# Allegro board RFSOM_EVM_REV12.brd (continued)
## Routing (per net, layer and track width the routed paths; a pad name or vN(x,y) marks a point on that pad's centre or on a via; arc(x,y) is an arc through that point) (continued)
JTAG_TDI: length 112.4
  TOP w0.173: U5.4 389.38,16.86 389.93,17.41 v1(389.93,17.81) ; J2.F23 v1(321.98,62.56)
  ART05 w0.14: v1(389.93,17.81) 389.93,18.64 381.25,27.32 365.64,27.32 363.13,29.84 363.13,48.2 357.91,53.42 357.91,63.9 354.32,67.49 335,67.49 331.91,64.4 322.55,64.4 321.98,63.83 v1(321.98,62.56)
  BOTTOM w0.173: v1(389.93,17.81) R7.2
JTAG_TDO: length 105.7
  TOP w0.173: v1(387.09,15.03) 386.59,15.54 U6.4 ; J2.B25 v1(328.33,61.29)
  ART05 w0.14: v1(387.09,15.03) 386.2,14.15 358.33,14.15 356.55,15.93 356.55,35.16 353.45,38.26 353.45,51.96 354.2,52.71 354.2,53.64 353.19,54.66 337.31,54.66 330.68,61.29 v1(328.33,61.29)
  BOTTOM w0.173: R8.2 386.32,17.81 387.09,17.04 v1(387.09,15.03)
JTAG_TMS: length 113.6
  TOP w0.173: v1(384.3,15.03) 383.79,15.54 U3.4 ; J2.D26 v1(324.52,58.75)
  ART05 w0.14: v1(384.3,15.03) 384.85,15.58 387.16,15.58 387.53,15.21 387.53,13.09 386.56,12.12 362.94,12.12 361.92,13.13 349.68,13.13 345.34,17.48 345.34,27.21 343.83,28.71 343.83,35.14 346.14,37.45 346.14,42.9 344,45.04 344,46.34 330.64,59.7 327.4,59.7 325.86,58.17 325.11,58.17 v1(324.52,58.75)
  BOTTOM w0.173: v1(384.3,15.03) 384.3,17.25 383.74,17.81 R9.2
LEDG0: length 119.2
  TOP w0.173: J1.C13 v1(228.1,76.53)
  TOP w0.381: R24.1 v1(283.21,-18.28)
  BOTTOM w0.381: v1(283.21,-18.28) 283.21,-12.04 278.63,-7.46 278.63,23.21 235.98,65.86 235.98,68.65 v1(228.1,76.53)
LEDG1: length 154.8
  TOP w0.173: J1.G7 v1(221.75,84.15)
  TOP w0.381: R27.1 v1(292.07,-18.28)
  ART10 w0.381: v1(221.75,84.15) 222.36,83.54 225.34,83.54 226.04,84.23 226.04,85.45 226.67,86.08 251.94,86.08 292.07,45.95 v1(292.07,-18.28)
LEDG2: length 141.5
  TOP w0.173: J1.G13 v1(223.02,76.53)
  TOP w0.381: R30.1 v1(300.94,-18.28)
  BOTTOM w0.381: v1(300.94,-18.28) 297.9,-18.28 291,-11.38 291,26.51 240.37,77.14 223.62,77.14 v1(223.02,76.53)
LEDG3: length 168.7
  TOP w0.173: J1.F7 v1(223.02,84.15)
  TOP w0.381: R33.1 v1(309.8,-18.28)
  ART10 w0.381: v1(223.02,84.15) 223.69,84.83 224.63,84.83 225.11,85.31 225.11,86.38 226.09,87.36 263.28,87.36 309.8,40.83 v1(309.8,-18.28)
M2_DEV_CLKN: length 57.8
  TOP w0.114: v1(341.04,-5.37) 340.85,-5.56 arc(340.68,-5.67) 340.48,-5.71 340.45,-5.71 arc(340.25,-5.67) 340.08,-5.56 C76.2 ; U13.15 339.17,28.96 arc(339.06,28.93) 338.96,28.87 338.94,28.85 arc(338.85,28.79) 338.73,28.76 337.62,28.76 arc(337.5,28.82) 337.44,28.94 337.44,29.07 arc(337.48,29.26) 337.59,29.42 v1(337.75,29.58)
  ART10 w0.102: v1(341.04,-5.37) 341.29,-5.62 arc(341.39,-5.69) 341.51,-5.71 343.5,-5.71 arc(344.26,-5.56) 344.91,-5.12 arc(345.4,-4.4) 345.56,-3.55 345.56,31.02 arc(345.52,31.25) 345.39,31.44 344.78,32.05 arc(344.64,32.15) 344.47,32.18 343.1,32.18 arc(343.01,32.14) 342.98,32.05 arc(342.94,31.96) 342.85,31.93 342.7,31.93 arc(342.61,31.96) 342.57,32.05 arc(342.53,32.14) 342.44,32.18 342.29,32.18 arc(342.2,32.14) 342.16,32.05 arc(342.13,31.96) 342.04,31.93 341.88,31.93 arc(341.79,31.96) 341.76,32.05 arc(341.72,32.14) 341.63,32.18 341.48,32.18 arc(341.39,32.14) 341.35,32.05 arc(341.31,31.96) 341.22,31.93 341.07,31.93 arc(340.98,31.96) 340.94,32.05 arc(340.91,32.14) 340.82,32.18 340.67,32.18 arc(340.58,32.14) 340.54,32.05 arc(340.5,31.96) 340.41,31.93 340.26,31.93 arc(340.17,31.96) 340.13,32.05 arc(340.09,32.14) 340,32.18 339.85,32.18 arc(339.76,32.14) 339.73,32.05 arc(339.69,31.96) 339.6,31.93 339.45,31.93 arc(339.36,31.96) 339.32,32.05 arc(339.28,32.14) 339.19,32.18 338.54,32.18 arc(338.34,32.14) 338.18,32.03 337.68,31.53 arc(337.48,31.23) 337.41,30.88 337.41,30.15 arc(337.45,29.93) 337.57,29.75 v1(337.75,29.58)
M2_DEV_CLKP: length 57.8
  TOP w0.114: U13.16 339.17,28.31 arc(339.06,28.33) 338.96,28.39 338.94,28.41 arc(338.85,28.48) 338.73,28.5 337.62,28.5 arc(337.31,28.63) 337.18,28.94 337.18,28.98 arc(337.13,29.19) 337.01,29.37 336.83,29.56 v1(336.83,29.58) ; v1(341.04,-6.28) 340.89,-6.14 arc(340.75,-6.04) 340.58,-6.01 340.43,-6.01 arc(340.23,-6.05) 340.07,-6.16 C77.2
  ART10 w0.102: v1(341.04,-6.28) 341.29,-6.03 arc(341.39,-5.97) 341.51,-5.94 343.5,-5.94 arc(344.36,-5.77) 345.08,-5.29 arc(345.61,-4.49) 345.8,-3.55 345.8,31.02 arc(345.74,31.34) 345.55,31.61 344.94,32.22 arc(344.73,32.37) 344.47,32.42 338.54,32.42 arc(338.25,32.36) 338.01,32.2 337.51,31.7 arc(337.26,31.32) 337.17,30.88 337.17,30.15 arc(337.13,29.93) 337.01,29.75 v1(336.83,29.58)
M2_NVME_DET: length 2.5
  TOP w0.173: J17.69 R64.2
M2_PERST: length 154
  TOP w0.173: v1(349.71,49.78) 351.38,49.78 R63.2 ; v1(326.42,-5.23) 325.6,-4.41 J17.50 ; J2.F7 v1(321.98,84.15)
  ART10 w0.135: v1(326.42,-5.23) 329.36,-8.17 345.79,-8.17 350.82,-3.13 350.82,33.15 349.71,34.27 v1(349.71,49.78)
  BOTTOM w0.173: v1(349.71,49.78) 344.69,54.79 331.86,54.79 329.65,57 318.62,57 314.84,60.78 314.84,78.71 317.13,81 320.87,81 321.3,81.43 321.3,83.47 v1(321.98,84.15)
NVME_ACT: length 2.4
  TOP w0.173: J17.10 v1(325.6,5.59)
  BOTTOM w0.508: v1(325.6,5.59) 325.99,5.2 D8.2
OSCI: length 8.3
  TOP w0.173: C11.1 389.15,-4.55 Y1.2 389.16,-3.3 389.46,-3 389.46,0.36 389.2,0.61 U2.2
OSCO: length 10.7
  TOP w0.173: C14.1 392.86,-7.06 Y1.1 392.86,-3.73 390.8,-1.68 390.8,0.48 390.18,1.11 U2.3
PHY_LED_1000: length 41.8
  TOP w0.173: RL15.1 382.2,69.28 v1(382.49,68.99) 382.49,68.3 381.84,67.65 U12.22
  ART10 w0.508: J16.11 402.15,54.03 385.66,54.03 381.7,57.99 381.7,60.32 383.16,61.77 383.16,68.32 v1(382.49,68.99)
PHY_LED_ACT: length 29.8
  TOP w0.173: RL18.1 383.2,68.16 v1(382.49,67.46) 382.24,67.21 U12.21
  ART03 w0.508: J16.14 402.37,73.25 391.94,73.25 386.15,67.46 v1(382.49,67.46)
PHY_MDC: length 67.5
  TOP w0.173: J2.D24 v1(324.52,62.56) ; v1(373.5,61.49) 375.06,61.49 375.3,61.73 375.77,61.73 376.45,62.41 U12.40
  BOTTOM w0.173: v1(324.52,62.56) 325.26,61.82 327.02,61.82 327.89,62.69 327.89,69.1 328.15,69.35 329.79,69.35 333.21,65.93 337.35,65.93 344.58,58.71 368.24,58.71 371.02,61.49 v1(373.5,61.49)
PHY_MDINT: length 4.4
  TOP w0.173: RL11.1 384.2,67.97 383.66,67.44 383.66,66.5 383.18,66.01 U12.20
PHY_MDIO: length 68.3
  TOP w0.173: U12.39 377.21,62.81 377.16,62.76 376.4,62.76 376.12,63.04 RL10.1 374.49,63.04 v1(374.28,63.25) ; J2.E24 v1(323.25,62.56)
  BOTTOM w0.173: v1(374.28,63.25) 369.89,63.25 365.77,59.14 345.09,59.14 337.77,66.46 333.37,66.46 330.09,69.74 328.07,69.74 327.5,69.17 327.5,63.42 327.28,63.2 324.46,63.2 323.83,62.56 v1(323.25,62.56)
PHY_RX_CLK: length 133.6
  TOP w0.173: U12.31 377.64,66.01 377.47,66.18 377.47,68.21 376.94,68.73 v1(376.94,68.99) 376.82,68.99 376.2,69.61 RL21.1 ; J2.G21 v1(320.71,66.37)
  BOTTOM w0.173: v1(320.71,66.37) 320.23,66.85 319.58,66.85 319,67.44 319,73.05 319.5,73.55 324.58,73.55 328.06,77.03 330.07,77.03 330.81,76.29 331.31,76.29 331.72,76.7 331.72,78.34 331.92,78.54 332.21,78.54 332.41,78.34 332.41,76.15 332.61,75.95 332.9,75.95 333.1,76.15 333.1,78.34 333.3,78.54 333.59,78.54 333.79,78.34 333.79,76.15 334,75.95 334.28,75.95 334.54,76.21 334.54,78.52 334.78,78.75 335.06,78.75 335.24,78.58 335.24,76.12 335.41,75.95 335.66,75.95 335.93,76.21 335.93,78.52 336.16,78.75 336.44,78.75 336.62,78.58 336.62,76.12 336.79,75.95 337.05,75.95 337.31,76.21 337.31,78.52 337.54,78.75 337.82,78.75 338,78.58 338,76.12 338.17,75.95 338.43,75.95 338.69,76.21 338.69,78.52 338.92,78.75 339.21,78.75 339.38,78.58 339.38,76.12 339.55,75.95 339.81,75.95 340.07,76.21 340.07,78.52 340.3,78.75 340.59,78.75 340.76,78.58 340.76,76.12 340.94,75.95 341.19,75.95 341.39,76.15 341.39,78.34 341.6,78.54 341.88,78.54 342.08,78.34 342.08,76.15 342.29,75.95 342.57,75.95 342.77,76.15 342.77,78.34 342.98,78.54 343.26,78.54 343.47,78.34 343.47,76.15 343.67,75.95 360.45,75.95 362.36,77.86 366.95,77.86 367.55,77.27 367.55,73.38 367.81,73.12 368.1,73.12 369.67,74.69 369.96,74.69 370.16,74.49 370.16,74.2 368.59,72.63 368.59,72.34 368.79,72.14 369.08,72.14 370.65,73.71 370.94,73.71 371.14,73.51 371.14,73.22 369.57,71.65 369.57,71.36 371.94,68.99 v1(376.94,68.99)
PHY_RX_CTRL: length 135.8
  TOP w0.173: U12.30 378.64,67 378.48,67.16 v1(378.48,67.46) 378,67.94 378,68.79 377.2,69.59 RL17.1 ; J2.F21 v1(323.25,65.1)
  BOTTOM w0.173: v1(378.48,67.46) 377.49,68.46 371.37,68.46 366.1,73.72 364.83,73.72 364.63,73.93 364.63,74.09 364.45,74.26 364.11,74.26 363.93,74.09 363.93,73.93 363.73,73.72 361.5,73.72 361.3,73.93 361.3,75.14 361.11,75.33 360.82,75.33 360.61,75.12 360.61,74.03 360.4,73.82 360.12,73.82 359.92,74.02 359.92,75.14 359.73,75.33 359.44,75.33 359.23,75.12 359.23,74.03 359.02,73.82 358.73,73.82 358.54,74.02 358.54,75.14 358.35,75.33 358.06,75.33 357.85,75.12 357.85,74.03 357.64,73.82 357.35,73.82 357.15,74.02 357.15,75.14 356.96,75.33 356.68,75.33 356.46,75.12 356.46,74.03 356.26,73.82 355.88,73.82 355.68,74.02 355.68,75.13 355.49,75.32 355.21,75.32 354.99,75.1 354.99,74.03 354.79,73.82 354.5,73.82 354.3,74.02 354.3,75.13 354.11,75.32 353.83,75.32 353.61,75.1 353.61,74.03 353.4,73.82 353.12,73.82 352.92,74.02 352.92,75.13 352.73,75.32 352.44,75.32 352.23,75.1 352.23,74.03 352.02,73.82 351.74,73.82 351.54,74.02 351.54,75.13 351.35,75.32 351.06,75.32 350.85,75.1 350.85,74.03 350.64,73.82 350.35,73.82 350.16,74.02 350.16,75.13 349.97,75.32 349.68,75.32 349.46,75.1 349.46,74.03 349.26,73.82 348.97,73.82 348.77,74.02 348.77,75.13 348.58,75.32 348.3,75.32 348.08,75.1 348.08,74.03 347.88,73.82 347.59,73.82 347.39,74.02 347.39,75.13 347.2,75.32 346.92,75.32 346.7,75.1 346.7,74.03 346.5,73.82 346.21,73.82 346.01,74.02 346.01,75.13 345.82,75.32 345.53,75.32 345.32,75.1 345.32,74.03 345.11,73.82 344.83,73.82 344.63,74.02 344.63,75.13 344.44,75.32 344.15,75.32 343.94,75.1 343.94,74.03 343.73,73.82 343.45,73.82 343.25,74.02 343.25,75.13 343.06,75.32 342.77,75.32 342.56,75.1 342.56,74.03 342.35,73.82 342.06,73.82 341.86,74.02 341.86,75.13 341.68,75.32 341.39,75.32 341.17,75.1 341.17,74.03 340.97,73.82 340.68,73.82 340.48,74.02 340.48,75.13 340.29,75.32 340.01,75.32 339.79,75.1 339.79,74.03 339.59,73.82 339.3,73.82 339.1,74.02 339.1,75.13 338.91,75.32 338.63,75.32 338.41,75.1 338.41,74.03 338.2,73.82 337.92,73.82 337.72,74.02 337.72,75.13 337.53,75.32 337.24,75.32 337.03,75.1 337.03,74.03 336.82,73.82 336.54,73.82 336.34,74.02 336.34,75.13 336.15,75.32 335.86,75.32 335.65,75.1 335.65,74.03 335.44,73.82 335.16,73.82 334.96,74.02 334.96,75.13 334.77,75.32 334.48,75.32 334.27,75.1 334.27,74.03 334.06,73.82 333.77,73.82 333.57,74.02 333.57,75.13 333.38,75.32 333.1,75.32 332.88,75.1 332.88,74.03 332.68,73.82 332.39,73.82 332.19,74.02 332.19,75.13 332,75.32 331.72,75.32 331.5,75.1 331.5,74.03 331.3,73.82 331.01,73.82 330.81,74.02 330.81,75.16 330.18,75.78 327.91,75.78 326.39,74.27 326.39,73.87 325.69,73.17 320.45,73.17 320.07,72.79 320.07,67.56 320.52,67.11 323.29,67.11 323.7,66.7 323.7,65.55 v1(323.25,65.1)
PHY_RXD0: length 133.4
  TOP w0.173: J2.E20 v1(323.25,66.37) ; U12.29 379.04,67.77 378.48,68.33 v1(378.48,68.99) 378.2,69.27 RL20.1
  BOTTOM w0.173: v1(323.25,66.37) 322.57,65.68 319.46,65.68 318.39,66.75 318.39,73.76 319.06,74.44 324.57,74.44 327.73,77.59 327.73,79.2 328.09,79.57 330.51,79.57 330.71,79.77 330.71,80.92 330.89,81.09 331.2,81.09 331.41,80.89 331.41,79.77 331.61,79.57 331.89,79.57 332.1,79.77 332.1,80.89 332.3,81.09 332.58,81.09 332.79,80.89 332.79,79.77 332.99,79.57 333.28,79.57 333.48,79.77 333.48,80.89 333.68,81.09 333.97,81.09 334.17,80.89 334.17,79.77 334.37,79.57 334.66,79.57 334.86,79.77 334.86,80.89 335.06,81.09 335.35,81.09 335.55,80.89 335.55,79.77 335.75,79.57 336.04,79.57 336.24,79.77 336.24,80.89 336.44,81.09 336.73,81.09 336.93,80.89 336.93,79.77 337.13,79.57 337.42,79.57 337.62,79.77 337.62,80.89 337.83,81.09 338.11,81.09 338.31,80.89 338.31,79.77 338.52,79.57 338.8,79.57 339,79.77 339,80.89 339.21,81.09 339.49,81.09 339.7,80.89 339.7,79.77 339.9,79.57 340.18,79.57 340.39,79.77 340.39,80.89 340.59,81.09 340.88,81.09 341.08,80.89 341.08,79.77 341.28,79.57 341.57,79.57 341.77,79.77 341.77,80.89 341.97,81.09 342.26,81.09 342.46,80.89 342.46,79.77 342.66,79.57 343.63,79.57 344.55,78.64 344.55,76.74 344.87,76.43 345.22,76.43 345.4,76.6 345.4,79.12 345.6,79.32 345.88,79.32 346.09,79.12 346.09,76.68 346.34,76.43 346.61,76.43 346.78,76.6 346.78,79.12 346.98,79.32 347.27,79.32 347.47,79.12 347.47,76.68 347.72,76.43 348.01,76.43 348.21,76.63 348.21,78.3 348.42,78.5 348.7,78.5 348.9,78.3 348.9,76.63 349.11,76.43 349.39,76.43 349.6,76.63 349.6,78.3 349.8,78.5 350.08,78.5 350.29,78.3 350.29,76.63 350.49,76.43 350.77,76.43 350.98,76.63 350.98,78.3 351.18,78.5 351.47,78.5 351.67,78.3 351.67,76.63 351.87,76.43 360.01,76.43 362.05,78.46 367.15,78.46 373.69,71.92 377.51,71.92 377.68,71.75 377.68,69.79 v1(378.48,68.99)
PHY_RXD1: length 134.2
  TOP w0.173: RL19.1 379.2,69.46 379.67,68.99 v1(379.84,68.99) 379.84,68.38 379.38,67.92 379.38,67.3 379.44,67.24 U12.28 ; J2.D22 v1(324.52,63.83)
  BOTTOM w0.173: v1(324.52,63.83) 324.08,63.39 318.55,63.39 316.57,65.37 316.57,74.91 318.82,77.17 323.42,77.17 323.93,77.67 323.93,78.23 324.26,78.57 324.26,82.22 325.51,83.46 329.65,83.46 331.38,85.2 331.38,93.64 333.63,95.89 335,95.89 335.21,95.69 335.21,95.15 335.41,94.95 335.7,94.95 335.9,95.15 335.9,95.69 336.1,95.89 336.39,95.89 336.59,95.69 336.59,95.15 336.79,94.95 337.08,94.95 337.28,95.15 337.28,95.69 337.48,95.89 337.77,95.89 337.97,95.69 337.97,95.15 338.17,94.95 338.46,94.95 338.66,95.15 338.66,95.69 338.86,95.89 339.15,95.89 339.35,95.69 339.35,95.15 339.55,94.95 339.84,94.95 340.04,95.15 340.04,95.69 340.25,95.89 340.53,95.89 340.73,95.69 340.73,95.15 340.94,94.95 341.22,94.95 341.43,95.15 341.43,95.69 341.63,95.89 341.91,95.89 342.12,95.69 342.12,95.15 342.32,94.95 342.6,94.95 342.77,95.12 342.77,95.79 342.97,95.99 343.26,95.99 343.46,95.79 343.46,95.19 343.7,94.95 343.99,94.95 344.19,95.15 344.19,95.69 344.39,95.89 369.72,95.89 375.88,89.74 375.88,76.44 380.7,71.62 380.7,69.84 v1(379.84,68.99)
PHY_RXD2: length 134
  TOP w0.173: RL16.1 380.2,69.56 380.77,68.99 v1(381.02,68.99) 381.02,68.73 380.44,68.15 380.44,67.36 380.24,67.16 U12.26 ; J2.B23 v1(328.33,62.56)
  BOTTOM w0.173: v1(328.33,62.56) 327.66,61.89 327.66,61.24 327.23,60.81 322.78,60.81 322.61,60.99 322.61,62.66 322.26,63 317.84,63 315.96,64.89 315.96,75.57 318.82,78.44 323.34,78.44 323.74,78.83 323.74,82.75 325.7,84.71 328.26,84.71 330.57,87.01 330.57,94.05 333.43,96.91 370.16,96.91 376.85,90.23 376.85,76.41 381.7,71.57 381.7,69.66 v1(381.02,68.99)
PHY_RXD3: length 135.1
  TOP w0.173: U12.25 380.64,67.08 v1(381.02,67.46) 381.02,67.69 381.55,68.22 381.55,69.2 381.2,69.56 RL14.1 ; J2.E22 v1(324.52,65.1)
  BOTTOM w0.173: v1(381.02,67.46) 381.02,67.96 380.52,68.46 379.71,68.46 379.39,68.78 379.39,69.41 379.7,69.72 379.7,71.61 374.95,76.35 374.95,82.2 364.16,93 357.66,93 356.69,93.96 351.88,93.96 351.68,93.76 351.68,93.13 351.47,92.92 351.19,92.92 350.98,93.13 350.98,93.76 350.78,93.96 350.5,93.96 350.29,93.76 350.29,93.13 350.09,92.92 349.81,92.92 349.6,93.13 349.6,93.76 349.4,93.96 349.11,93.96 348.91,93.76 348.91,93.13 348.71,92.92 348.42,92.92 348.22,93.13 348.22,93.76 348.02,93.96 347.73,93.96 347.53,93.76 347.53,93.13 347.33,92.92 347.04,92.92 346.84,93.13 346.84,93.76 346.64,93.96 346.35,93.96 346.15,93.76 346.15,93.13 345.95,92.92 345.66,92.92 345.46,93.13 345.46,93.76 345.26,93.96 344.97,93.96 344.77,93.76 344.77,93.13 344.56,92.92 344.28,92.92 344.08,93.13 344.08,93.76 343.87,93.96 343.59,93.96 343.38,93.76 343.38,93.13 343.18,92.92 342.9,92.92 342.69,93.13 342.69,93.76 342.49,93.96 342.21,93.96 342,93.76 342,93.13 341.8,92.92 341.51,92.92 341.31,93.13 341.31,93.76 341.11,93.96 340.82,93.96 340.62,93.76 340.62,93.13 340.42,92.92 340.13,92.92 339.93,93.13 339.93,93.76 339.73,93.96 339.44,93.96 339.24,93.76 339.24,93.13 339.04,92.92 338.75,92.92 338.55,93.13 338.55,93.76 338.35,93.96 338.06,93.96 337.86,93.76 337.86,93.29 337.69,93.11 337.44,93.11 337.24,93.32 337.24,93.69 336.99,93.94 336.75,93.94 336.58,93.76 336.58,93.39 336.37,93.19 336.09,93.19 335.79,93.5 335.79,93.76 335.58,93.96 334.72,93.96 332.36,91.61 332.36,84.73 329.86,82.23 325.72,82.23 325.21,81.72 325.21,77.69 324.71,77.19 324.18,77.19 323.74,76.75 323.74,76.37 323.27,75.9 318.72,75.9 317.17,74.35 317.17,65.58 318.48,64.27 323.69,64.27 v1(324.52,65.1)
PHY_TRXN0: length 14
  TOP w0.114: U12.10 382.24,61.06 382.17,61 382.17,60.66 383.4,59.43 392.52,59.43 392.78,59.69 392.69,59.96 J16.3
PHY_TRXN1: length 13.6
  TOP w0.114: v1(389.18,62.92) 388.95,62.7 387.88,62.7 387.52,62.34 387.52,61.62 387.32,61.42 385.9,61.42 385.69,61.62 385.69,62.34 385.33,62.7 384.64,62.7 384.2,63.14 383.65,63.14 383.59,63.21 U12.13
  BOTTOM w0.114: v1(389.18,62.92) 389.4,62.7 390.06,62.7 390.38,63.02 390.38,64.03 390.25,64.16 390.21,64.16 390.07,64.3 390.07,64.49 390.21,64.62 390.25,64.62 390.38,64.75 390.38,65.14 390.89,65.65 J16.7
PHY_TRXN2: length 13.6
  TOP w0.114: U12.16 383.59,64.41 383.65,64.34 385.31,64.34 385.61,64.64 385.61,65.39 386.22,66 389.44,66 389.96,65.48 389.96,64.73 390.16,64.52 392.52,64.52 393.03,64.01 393.19,63.98 J16.6
PHY_TRXN3: length 13.8
  TOP w0.114: J16.9 392.62,67.62 392.71,67.35 392.41,67.05 389.65,67.05 389.45,67.25 389.45,68.1 389.09,68.46 387.14,68.46 384.22,65.54 383.65,65.54 383.59,65.61 U12.19
PHY_TRXP0: length 14.1
  TOP w0.114: J16.2 393.45,59.58 392.97,59.5 392.64,59.16 383.29,59.16 381.91,60.55 381.91,61 381.84,61.06 U12.9
PHY_TRXP1: length 13.7
  TOP w0.114: U12.12 383.59,62.81 383.65,62.88 384.09,62.88 384.53,62.44 385.22,62.44 385.43,62.23 385.43,61.51 385.78,61.15 387.43,61.15 387.79,61.51 387.79,62.23 387.99,62.44 388.95,62.44 v1(389.18,62.21)
  BOTTOM w0.114: J16.4 390.7,61.84 390.11,62.44 389.4,62.44 v1(389.18,62.21)
PHY_TRXP2: length 13.7
  TOP w0.114: J16.5 392.62,63.69 392.71,63.96 392.41,64.26 390.05,64.26 389.69,64.62 389.69,65.37 389.33,65.73 386.33,65.73 385.88,65.28 385.88,64.53 385.43,64.08 383.65,64.08 383.59,64.01 U12.15
PHY_TRXP3: length 13.7
  TOP w0.114: U12.18 383.59,65.21 383.65,65.28 384.33,65.28 387.25,68.19 388.98,68.19 389.18,67.99 389.18,67.14 389.54,66.78 392.52,66.78 393.03,67.3 393.19,67.33 J16.8
PHY_TX_CLK: length 104.2
  TOP w0.173: U12.33 377.33,65.21 376.98,65.56 375.36,65.56 v1(374.89,66.03) ; J2.F19 v1(321.98,68.91)
  BOTTOM w0.173: v1(321.98,68.91) 322.63,69.56 322.63,70.23 323.04,70.64 326.12,70.64 326.3,70.81 326.3,71.81 326.74,72.25 330.11,72.25 330.45,71.91 331.7,71.91 334.18,69.42 334.7,69.42 334.97,69.7 334.97,70.27 335.18,70.48 335.46,70.48 335.66,70.27 335.66,69.59 335.84,69.42 336.08,69.42 336.35,69.7 336.35,70.27 336.56,70.48 336.84,70.48 337.05,70.27 337.05,69.59 337.22,69.42 337.46,69.42 337.74,69.7 337.74,70.27 337.94,70.48 338.22,70.48 338.43,70.27 338.43,69.59 338.6,69.42 338.84,69.42 339.12,69.7 339.12,70.27 339.32,70.48 339.56,70.48 339.74,70.3 339.74,69.62 339.94,69.42 340.97,69.42 343.88,66.51 345.52,66.51 345.73,66.72 345.73,67.25 345.93,67.45 346.21,67.45 346.47,67.2 346.47,66.27 346.64,66.1 346.9,66.1 347.11,66.3 347.11,67.25 347.31,67.45 347.6,67.45 347.85,67.2 347.85,66.27 348.02,66.1 348.29,66.1 348.49,66.3 348.49,67.25 348.69,67.45 348.98,67.45 349.23,67.2 349.23,66.27 349.4,66.1 349.67,66.1 349.87,66.3 349.87,67.25 350.07,67.45 350.36,67.45 350.61,67.2 350.61,66.27 350.78,66.1 351.05,66.1 351.25,66.3 351.25,67.25 351.46,67.45 351.74,67.45 351.99,67.2 351.99,66.27 352.17,66.1 352.43,66.1 352.63,66.3 352.63,67.25 352.84,67.45 353.12,67.45 353.33,67.25 353.33,66.66 353.5,66.49 353.84,66.49 354.02,66.66 354.02,67.25 354.22,67.45 354.5,67.45 354.76,67.2 354.76,66.25 354.94,66.07 355.2,66.07 355.4,66.27 355.4,67.25 355.6,67.45 355.89,67.45 356.14,67.2 356.14,66.31 356.31,66.13 356.58,66.13 356.78,66.34 356.78,67.25 356.98,67.45 357.27,67.45 357.52,67.2 357.52,66.31 357.69,66.13 357.96,66.13 358.16,66.34 358.16,67.25 358.36,67.45 358.65,67.45 358.9,67.2 358.9,66.31 359.07,66.13 359.34,66.13 359.54,66.34 359.54,67.25 359.75,67.45 360.03,67.45 360.28,67.2 360.28,66.31 360.46,66.13 360.72,66.13 360.93,66.34 360.93,67.25 361.13,67.45 361.41,67.45 361.67,67.2 361.67,66.31 361.84,66.13 362.1,66.13 362.31,66.34 362.31,67.25 362.51,67.45 362.8,67.45 363.05,67.2 363.05,66.31 363.22,66.13 363.48,66.13 363.69,66.34 363.69,67.25 363.89,67.45 364.18,67.45 364.43,67.2 364.43,66.31 364.6,66.13 364.87,66.13 365.07,66.34 365.07,67.25 365.27,67.45 365.56,67.45 365.81,67.2 365.81,66.31 365.98,66.13 366.25,66.13 366.45,66.34 366.45,67.25 366.65,67.45 366.94,67.45 367.19,67.2 367.19,66.31 367.37,66.13 367.63,66.13 367.83,66.34 367.83,67.25 368.04,67.45 368.32,67.45 368.52,67.25 368.52,66.71 369.2,66.03 v1(374.89,66.03)
PHY_TX_CTRL: length 104.3
  TOP w0.173: J2.C21 v1(325.79,66.37) ; v1(375.89,66.03) 377.02,66.03 377.44,65.61 U12.32
  BOTTOM w0.173: v1(375.89,66.03) 375.1,66.82 370.1,66.82 366.72,70.2 365.25,70.2 365.04,70 365.04,68.13 364.84,67.93 364.56,67.93 364.35,68.13 364.35,69.35 364.15,69.55 363.86,69.55 363.66,69.35 363.66,68.13 363.46,67.93 363.17,67.93 362.97,68.13 362.97,69.35 362.77,69.55 362.48,69.55 362.28,69.35 362.28,68.13 362.08,67.93 361.79,67.93 361.59,68.13 361.59,69.35 361.39,69.55 361.1,69.55 360.9,69.35 360.9,68.13 360.7,67.93 360.41,67.93 360.21,68.13 360.21,69.35 360,69.55 359.72,69.55 359.52,69.35 359.52,68.13 359.31,67.93 359.03,67.93 358.83,68.13 358.83,70 358.62,70.2 356.37,70.2 356.16,70 356.16,68.2 355.96,68 355.67,68 355.47,68.2 355.47,70 355.27,70.2 350.37,70.2 350.17,70 350.17,68.21 349.97,68.01 349.68,68.01 349.48,68.21 349.48,69.22 349.28,69.43 348.99,69.43 348.79,69.22 348.79,68.21 348.58,68.01 348.3,68.01 348.1,68.21 348.1,69.22 347.89,69.43 347.61,69.43 347.4,69.22 347.4,68.21 347.2,68.01 346.92,68.01 346.71,68.21 346.71,69.22 346.51,69.43 346.23,69.43 346.02,69.22 346.02,68.21 345.82,68.01 345.53,68.01 345.33,68.21 345.33,69.22 345.13,69.43 344.84,69.43 344.64,69.22 344.64,68.21 344.44,68.01 343.29,68.01 339.07,72.22 330.93,72.22 329.97,73.19 326.89,73.19 325.6,71.9 321.8,71.9 321.54,71.64 321.54,68.5 321.71,68.33 323.77,68.33 323.98,68.53 323.98,69.04 324.29,69.35 326.09,69.35 326.26,69.18 326.26,66.84 v1(325.79,66.37)
PHY_TXD0: length 104.8
  TOP w0.173: J2.G19 v1(320.71,68.91) ; v1(375.89,65.03) 376.95,65.03 377.17,64.81 U12.34
  BOTTOM w0.173: v1(375.89,65.03) 376.39,65.53 376.39,66.63 375.62,67.41 371.13,67.41 365.32,73.21 363.87,73.21 363.67,73.01 363.67,71.15 363.47,70.95 363.18,70.95 362.98,71.15 362.98,72.11 362.81,72.28 362.53,72.28 362.29,72.03 362.29,71.15 362.09,70.95 361.8,70.95 361.6,71.15 361.6,72.11 361.43,72.28 361.15,72.28 360.91,72.03 360.91,71.15 360.7,70.95 360.42,70.95 360.22,71.15 360.22,72.11 360.04,72.28 359.77,72.28 359.53,72.03 359.53,71.15 359.32,70.95 359.04,70.95 358.83,71.15 358.83,73.01 358.63,73.21 356.5,73.21 356.33,73.04 356.33,71.1 356.14,70.9 349.66,70.9 349.13,70.37 348.84,70.37 348.64,70.57 348.64,72.99 348.43,73.21 348.14,73.21 347.95,73.02 347.95,70.57 347.75,70.37 347.46,70.37 347.26,70.57 347.26,72.99 347.04,73.21 346.76,73.21 346.57,73.02 346.57,70.57 346.37,70.37 346.08,70.37 345.88,70.57 345.88,72.99 345.66,73.21 345.38,73.21 345.19,73.02 345.19,70.57 344.98,70.37 344.7,70.37 344.5,70.57 344.5,72.99 344.28,73.21 343.99,73.21 343.8,73.02 343.8,70.57 343.6,70.37 343.32,70.37 343.11,70.57 343.11,73 342.94,73.18 330.59,73.18 330.26,73.5 330.26,74.27 329.95,74.58 327.9,74.58 327.62,74.29 327.62,73.77 327.35,73.51 326.6,73.51 325.36,72.28 321.56,72.28 321.16,71.88 321.16,69.36 v1(320.71,68.91)
PHY_TXD1: length 104.9
  TOP w0.173: J2.C17 v1(327.06,71.45) ; v1(374.89,65.03) 375.39,64.53 376.92,64.53 377.04,64.41 U12.35
  BOTTOM w0.173: v1(327.06,71.45) 327.52,71.91 329.84,71.91 330.32,71.43 331.14,71.43 334.16,68.41 338.92,68.41 339.27,68.06 339.56,68.06 340.17,68.68 340.45,68.68 340.66,68.47 340.66,68.19 340.04,67.57 340.04,67.29 340.25,67.09 340.53,67.09 341.14,67.7 341.43,67.7 341.63,67.5 341.63,67.21 341.02,66.6 341.02,66.31 341.22,66.11 341.51,66.11 342.12,66.72 342.41,66.72 342.61,66.52 342.61,66.23 342,65.62 342,65.33 342.2,65.13 342.49,65.13 343.1,65.74 343.39,65.74 343.59,65.54 343.59,65.25 342.98,64.64 342.98,64.36 343.66,63.67 344.33,63.67 344.53,63.87 344.53,65.04 344.75,65.26 345.04,65.26 345.22,65.07 345.22,63.87 345.43,63.67 345.71,63.67 345.91,63.87 345.91,65.04 346.13,65.26 346.42,65.26 346.61,65.07 346.61,63.87 346.81,63.67 347.09,63.67 347.3,63.87 347.3,65.04 347.51,65.26 347.8,65.26 347.99,65.07 347.99,63.87 348.19,63.67 348.48,63.67 348.68,63.87 348.68,65.04 348.89,65.26 349.18,65.26 349.37,65.07 349.37,63.87 349.57,63.67 349.86,63.67 350.06,63.87 350.06,65.04 350.28,65.26 350.56,65.26 350.75,65.07 350.75,63.87 350.95,63.67 351.24,63.67 351.44,63.87 351.44,65.04 351.66,65.26 351.94,65.26 352.13,65.07 352.13,63.87 352.33,63.67 352.62,63.67 352.82,63.87 352.82,65.04 353.04,65.26 353.33,65.26 353.51,65.07 353.51,63.87 353.72,63.67 354,63.67 354.2,63.87 354.2,65.04 354.42,65.26 354.71,65.26 354.9,65.07 354.9,63.87 355.1,63.67 355.38,63.67 355.59,63.87 355.59,65.04 355.8,65.26 356.09,65.26 356.28,65.07 356.28,63.87 356.48,63.67 356.77,63.67 356.97,63.87 356.97,65.04 357.18,65.26 357.47,65.26 357.66,65.07 357.66,63.87 357.86,63.67 358.15,63.67 358.35,63.87 358.35,65.04 358.57,65.26 358.85,65.26 359.04,65.07 359.04,63.87 359.24,63.67 359.53,63.67 359.73,63.87 359.73,65.04 359.95,65.26 360.23,65.26 360.42,65.07 360.42,63.87 360.63,63.67 360.91,63.67 361.11,63.87 361.11,65.04 361.33,65.26 361.62,65.26 361.8,65.07 361.8,63.87 362.01,63.67 362.29,63.67 362.5,63.87 362.5,65.04 362.71,65.26 363,65.26 363.19,65.07 363.19,63.87 363.39,63.67 363.67,63.67 363.88,63.87 363.88,65.04 364.09,65.26 364.38,65.26 364.57,65.07 364.57,63.87 364.77,63.67 365.58,63.67 366.94,65.03 v1(374.89,65.03)
PHY_TXD2: length 104.6
  TOP w0.173: U12.36 377.96,64.03 v1(375.89,64.03) ; J2.B17 v1(328.33,71.45)
  ART05 w0.14: v1(328.33,71.45) 327.83,71.96 321.56,71.96 321.34,72.19 321.34,74.17 321.64,74.47 324.69,74.47 324.95,74.74 324.95,79.21 325.42,79.68 329.79,79.68 331.06,80.95 331.06,88.54 335.66,93.14 361.92,93.14 370.43,84.63 370.43,66.16 372.07,64.53 375.4,64.53 v1(375.89,64.03)
PHY_TXD3: length 104.5
  TOP w0.173: U12.37 377.56,63.61 377.44,63.73 376.55,63.73 376.35,63.53 375.4,63.53 v1(374.89,64.03) ; J2.C23 v1(327.06,63.83)
  BOTTOM w0.173: v1(374.89,64.03) 367.95,64.03 367.57,63.64 367.57,63.36 368.08,62.84 368.08,62.55 367.88,62.35 367.6,62.35 367.08,62.87 366.79,62.87 366.59,62.66 366.59,62.38 367.11,61.86 367.11,61.57 366.9,61.37 366.62,61.37 366.1,61.89 365.81,61.89 365.62,61.69 364.61,61.69 364.41,61.49 364.41,60.26 364.19,60.04 363.91,60.04 363.72,60.23 363.72,61.49 363.52,61.69 363.23,61.69 363.03,61.49 363.03,60.26 362.81,60.04 362.53,60.04 362.34,60.23 362.34,61.49 362.13,61.69 361.85,61.69 361.65,61.49 361.65,60.26 361.43,60.04 361.14,60.04 360.96,60.23 360.96,61.49 360.75,61.69 360.47,61.69 360.26,61.49 360.26,60.26 360.05,60.04 359.76,60.04 359.57,60.23 359.57,61.49 359.37,61.69 359.09,61.69 358.88,61.49 358.88,60.26 358.67,60.04 358.38,60.04 358.19,60.23 358.19,61.49 357.99,61.69 357.7,61.69 357.5,61.49 357.5,60.26 357.28,60.04 357,60.04 356.81,60.23 356.81,61.49 356.61,61.69 356.32,61.69 356.12,61.49 356.12,60.26 355.9,60.04 355.62,60.04 355.43,60.23 355.43,61.49 355.23,61.69 354.94,61.69 354.74,61.49 354.74,60.26 354.52,60.04 354.23,60.04 354.05,60.23 354.05,61.49 353.84,61.69 352.72,61.69 352.52,61.49 352.52,60.19 352.31,59.99 352.03,59.99 351.83,60.19 351.83,61.49 351.62,61.69 351.34,61.69 351.13,61.49 351.13,60.19 350.93,59.99 350.65,59.99 350.44,60.19 350.44,61.49 350.24,61.69 349.95,61.69 349.75,61.49 349.75,60.19 349.55,59.99 349.26,59.99 349.06,60.19 349.06,61.49 348.86,61.69 348.57,61.69 348.37,61.49 348.37,60.19 348.17,59.99 347.88,59.99 347.68,60.19 347.68,61.49 347.48,61.69 347.19,61.69 346.99,61.49 346.99,60.19 346.79,59.99 346.5,59.99 346.3,60.19 346.3,61.49 346.1,61.69 343.57,61.69 338.15,67.11 333.51,67.11 330,70.62 327.75,70.62 326.59,69.47 326.59,64.3 v1(327.06,63.83)
PHY_XTAL_IN: length 8.8
  TOP w0.173: 380.09,59.91 380.09,60.71 380.24,60.86 U12.5
  TOP w0.254: Y2.2 378.8,55.59 378.55,55.85 378.55,57.6 C57.2 378.51,58.25 378.51,58.68 379.2,59.36 379.54,59.36 380.09,59.91
PHY_XTAL_OUT: length 8.8
  TOP w0.173: 379.69,60.25 379.69,60.87 379.84,61.03 U12.4
  TOP w0.254: Y2.1 377.72,55.59 377.98,55.85 377.98,57.62 C58.2 378.01,58.25 378.01,58.94 378.92,59.85 379.29,59.85 379.69,60.25
PPS_1S_GPS: length 94.3
  TOP w0.173: UG1.3 v1(235.24,-4.73) ; J1.B9 v1(229.37,81.61)
  ART03 w0.135: v1(235.24,-4.73) 235.24,79.99 233,82.23 229.99,82.23 v1(229.37,81.61)
PS_DONE: length 34.7
  TOP w0.173: J2.C27 v1(325.79,58.75) ; R75.2 v1(353.63,63.23)
  ART05 w0.14: v1(353.63,63.23) 350.89,65.96 335.1,65.96 331.19,62.05 327.08,62.05 326.47,61.44 326.47,59.43 v1(325.79,58.75)
PS_ERR_STAT: length 31.6
  TOP w0.173: J2.C25 v1(327.06,61.29) ; R81.2 v1(353.58,52.97)
  ART05 w0.14: v1(353.58,52.97) 352.78,53.77 337.16,53.77 330.7,60.23 328.13,60.23 v1(327.06,61.29)
PS_ERROR: length 39
  TOP w0.173: v1(354.29,56.44) 353.94,56.44 353.63,56.75 R79.2 ; J2.G23 v1(320.71,62.56)
  BOTTOM w0.173: v1(354.29,56.44) 333.71,56.44 330.5,59.64 322.61,59.64 321.36,60.88 321.36,61.91 v1(320.71,62.56)
PS_MODE0: length 41.3
  TOP w0.173: J2.G25 v1(320.71,60.02)
  ART05 w0.14: v1(320.71,60.02) 320.05,60.68 320.05,65.43 320.51,65.89 331.62,65.89 338.4,72.67 351.03,72.67 SWC3.1
PS_MODE1: length 39.7
  TOP w0.173: J2.E26 v1(323.25,58.75)
  ART05 w0.14: v1(323.25,58.75) 321.56,60.44 321.56,61.1 321.55,61.11 321.55,65.28 321.8,65.53 332.28,65.53 335.78,69.03 SWC2.1
PS_MODE2: length 148.3
  TOP w0.173: J2.F25 v1(323.25,61.29)
  ART05 w0.14: SWC1.3 401.33,-1.59 394.67,5.08 394.67,14.39 392.85,16.21 358.29,16.21 357.3,17.2 357.3,36.18 354.96,38.52 354.96,47.61 355.9,48.55 355.9,64.75 353.67,66.98 335.3,66.98 331.69,63.37 325.98,63.37 324.57,61.96 323.92,61.96 v1(323.25,61.29)
PS_MODE3: length 140.6
  TOP w0.173: J2.D28 v1(324.52,56.21)
  ART05 w0.14: SWC1.1 403.91,-4.13 401.99,-6.05 394.44,-6.05 393.42,-5.03 393.42,8.69 392.28,9.83 361.92,9.83 361.29,10.46 348.01,10.46 339.71,18.76 339.71,26.72 341.98,28.98 341.98,35.07 344.03,37.12 344.03,42.48 342.24,44.26 342.24,45.46 329.51,58.19 328.14,58.19 326.34,56.39 326.34,56.06 325.95,55.67 325.06,55.67 v1(324.52,56.21)
PS_POR: length 100.1
  TOP w0.173: R209.1 374.85,61.16 v1(374.49,60.81) ; J2.G11 v1(321.98,79.07)
  ART05 w0.14: v1(374.49,60.81) 375.27,61.58 375.27,62.75 376.46,63.94 376.46,65.26 376.21,65.52 372.61,65.52 371.07,67.05 371.07,90.6 365.99,95.68 336.14,95.68 330.43,89.97 327,89.97 326.36,89.33 326.36,81.43 325.73,80.8 325.25,80.8 324.23,79.78 323.14,79.78 322.43,79.07 v1(321.98,79.07)
PS_POR_B: length 2.4
  TOP w0.173: U12.1 378.64,61.42 378.38,61.16 R209.2
RX_00_N: length 76.8
  TOP w0.114: v1(188.91,-18.62) 188.74,-18.79 arc(188.57,-18.91) 188.37,-18.95 188.12,-18.95 arc(187.88,-18.9) 187.69,-18.77 LAB42.2 187.25,-18.82 arc(187.1,-18.91) 186.93,-18.95 186.9,-18.95 arc(186.73,-18.91) 186.58,-18.82 CAB49.1 ; J1.C46 v1(228.1,34.62)
  ART10 w0.102: v1(228.1,34.62) 228.1,34.35 arc(228.03,34.18) 227.85,34.11 226.89,34.11 arc(226.3,33.99) 225.81,33.66 225.65,33.5 arc(225.44,33.19) 225.37,32.82 225.37,30.13 225.37,29.36 arc(225.33,29.15) 225.21,28.98 205.49,9.26 arc(205.16,8.76) 205.04,8.18 205.04,-6.17 arc(204.97,-6.5) 204.78,-6.78 192.86,-18.71 arc(192.58,-18.9) 192.24,-18.96 189.48,-18.96 arc(189.26,-18.92) 189.08,-18.8 v1(188.91,-18.62)
RX_00_P: length 76.8
  TOP w0.114: J1.B46 v1(228.1,33.35) ; v1(188.91,-19.54) 188.74,-19.37 arc(188.57,-19.26) 188.37,-19.22 188.12,-19.22 arc(187.88,-19.26) 187.69,-19.39 LAB42.1 187.25,-19.35 arc(187.1,-19.25) 186.93,-19.22 186.9,-19.22 arc(186.73,-19.25) 186.58,-19.35 CAB51.1
  ART10 w0.102: v1(228.1,33.35) 228.1,33.62 arc(228.03,33.8) 227.85,33.87 226.89,33.87 arc(226.39,33.77) 225.98,33.49 225.82,33.33 arc(225.66,33.09) 225.6,32.82 225.6,29.56 225.6,29.56 225.6,29.36 arc(225.54,29.06) 225.38,28.82 205.65,9.09 arc(205.37,8.67) 205.28,8.18 205.28,-6.17 arc(205.19,-6.59) 204.95,-6.95 193.03,-18.88 arc(192.67,-19.12) 192.24,-19.2 189.48,-19.2 arc(189.26,-19.24) 189.08,-19.36 v1(188.91,-19.54)
RX_01_N: length 64.8
  TOP w0.114: v1(188.91,-8.62) 188.74,-8.79 arc(188.57,-8.91) 188.37,-8.95 188.12,-8.95 arc(187.88,-8.9) 187.69,-8.77 LAB44.2 187.25,-8.82 arc(187.1,-8.91) 186.93,-8.95 186.9,-8.95 arc(186.73,-8.91) 186.58,-8.82 CAB52.1 ; J1.G46 v1(223.02,34.62)
  ART10 w0.102: v1(188.91,-8.62) 189.08,-8.8 arc(189.26,-8.92) 189.48,-8.96 192.54,-8.96 arc(193.06,-8.86) 193.5,-8.56 201.15,-0.92 arc(201.35,-0.61) 201.42,-0.25 201.42,13.45 arc(201.51,13.91) 201.78,14.3 221.23,33.75 arc(221.62,34.01) 222.08,34.11 222.77,34.11 arc(222.95,34.18) 223.02,34.35 v1(223.02,34.62)
RX_01_P: length 64.8
  TOP w0.114: v1(188.91,-9.54) 188.74,-9.37 arc(188.57,-9.26) 188.37,-9.22 188.12,-9.22 arc(187.88,-9.26) 187.69,-9.39 LAB44.1 187.25,-9.35 arc(187.1,-9.25) 186.93,-9.22 186.9,-9.22 arc(186.73,-9.25) 186.58,-9.35 CAB54.1 ; J1.F46 v1(223.02,33.35)
  ART10 w0.102: v1(223.02,33.35) 223.02,33.62 arc(222.95,33.8) 222.77,33.87 222.08,33.87 arc(221.71,33.8) 221.39,33.59 201.94,14.13 arc(201.73,13.82) 201.66,13.45 201.66,-0.25 arc(201.57,-0.7) 201.31,-1.08 193.67,-8.73 arc(193.15,-9.08) 192.54,-9.2 189.48,-9.2 arc(189.26,-9.24) 189.08,-9.36 v1(188.91,-9.54)
RX_02_N: length 63.3
  TOP w0.114: CAB55.1 186.58,1.18 arc(186.73,1.09) 186.9,1.05 186.93,1.05 arc(187.1,1.09) 187.25,1.18 LAB46.2 187.69,1.23 arc(187.88,1.1) 188.12,1.05 188.37,1.05 arc(188.57,1.09) 188.74,1.21 v1(188.91,1.38) ; J1.C42 v1(228.1,39.7)
  ART10 w0.102: v1(228.1,39.7) 228.1,39.43 arc(228.03,39.26) 227.85,39.19 226.23,39.19 arc(225.79,39.1) 225.4,38.84 225.39,38.82 arc(225.13,38.44) 225.04,38 225.04,37.21 arc(225,36.98) 224.86,36.78 224.84,36.76 arc(224.64,36.62) 224.41,36.58 220.64,36.58 arc(220.06,36.46) 219.56,36.13 197.09,13.65 arc(196.86,13.31) 196.77,12.9 196.77,8.06 arc(196.72,7.81) 196.58,7.6 190.29,1.3 arc(189.99,1.11) 189.65,1.04 189.48,1.04 arc(189.26,1.08) 189.08,1.2 v1(188.91,1.38)
RX_02_P: length 63.3
  TOP w0.114: v1(188.91,0.46) 188.74,0.63 arc(188.57,0.74) 188.37,0.78 188.12,0.78 arc(187.88,0.74) 187.69,0.61 LAB46.1 187.25,0.65 arc(187.1,0.75) 186.93,0.78 186.9,0.78 arc(186.73,0.75) 186.58,0.65 CAB57.1 ; J1.B42 v1(228.1,38.43)
  ART10 w0.102: v1(188.91,0.46) 189.08,0.64 arc(189.26,0.76) 189.48,0.8 189.65,0.8 arc(190,0.86) 190.32,1.02 190.34,1.02 196.75,7.43 arc(196.94,7.72) 197.01,8.06 197.01,12.9 arc(197.07,13.21) 197.25,13.48 219.73,35.96 arc(220.15,36.24) 220.64,36.34 224.41,36.34 arc(224.73,36.4) 225.01,36.59 225.03,36.61 arc(225.22,36.89) 225.28,37.21 225.28,38 arc(225.35,38.35) 225.55,38.66 225.57,38.67 arc(225.88,38.88) 226.23,38.95 227.85,38.95 arc(228.03,38.88) 228.1,38.7 v1(228.1,38.43)
RX_03_N: length 50.2
  TOP w0.114: v1(188.91,11.38) 188.74,11.21 arc(188.57,11.09) 188.37,11.05 188.12,11.05 arc(187.88,11.1) 187.69,11.23 LAB48.2 187.25,11.18 arc(187.1,11.09) 186.93,11.05 186.9,11.05 arc(186.73,11.09) 186.58,11.18 CAB58.1 ; J1.G42 v1(223.02,39.7)
  ART10 w0.102: v1(188.91,11.38) 189.08,11.2 arc(189.26,11.08) 189.48,11.04 189.88,11.04 arc(190.37,11.13) 190.78,11.41 218.11,38.74 arc(218.6,39.07) 219.19,39.19 222.77,39.19 arc(222.95,39.26) 223.02,39.43 v1(223.02,39.7)
RX_03_P: length 50.2
  TOP w0.114: CAB60.1 186.58,10.65 arc(186.73,10.75) 186.9,10.78 186.93,10.78 arc(187.1,10.75) 187.25,10.65 LAB48.1 187.69,10.61 arc(187.88,10.74) 188.12,10.78 188.37,10.78 arc(188.57,10.74) 188.74,10.63 v1(188.91,10.46) ; J1.F42 v1(223.02,38.43)
  ART10 w0.102: v1(223.02,38.43) 223.02,38.7 arc(222.95,38.88) 222.77,38.95 219.19,38.95 arc(218.69,38.85) 218.28,38.57 190.95,11.25 arc(190.46,10.92) 189.88,10.8 189.48,10.8 arc(189.26,10.76) 189.08,10.64 v1(188.91,10.46)
RX_04_N: length 53.9
  TOP w0.114: v1(188.91,21.38) 188.74,21.21 arc(188.57,21.09) 188.37,21.05 188.12,21.05 arc(187.88,21.1) 187.69,21.23 LAB50.2 187.25,21.18 arc(187.1,21.09) 186.93,21.05 186.9,21.05 arc(186.73,21.09) 186.58,21.18 CAB61.1 ; J1.C38 v1(228.1,44.78)
  ART10 w0.102: v1(188.91,21.38) 189.08,21.2 arc(189.26,21.08) 189.48,21.04 194.63,21.04 arc(195.12,21.13) 195.54,21.41 215.41,41.29 arc(215.91,41.62) 216.5,41.73 224.9,41.73 arc(225.21,41.8) 225.48,41.97 225.5,41.99 arc(225.67,42.25) 225.73,42.56 225.73,43.24 arc(225.81,43.63) 226.03,43.95 226.05,43.97 arc(226.37,44.19) 226.76,44.27 227.85,44.27 arc(228.03,44.34) 228.1,44.51 v1(228.1,44.78)
RX_04_P: length 53.9
  TOP w0.114: v1(188.91,20.46) 188.74,20.63 arc(188.57,20.74) 188.37,20.78 188.12,20.78 arc(187.88,20.74) 187.69,20.61 LAB50.1 187.25,20.65 arc(187.1,20.75) 186.93,20.78 186.9,20.78 arc(186.73,20.75) 186.58,20.65 CAB63.1 ; J1.B38 v1(228.1,43.51)
  ART10 w0.102: v1(188.91,20.46) 189.08,20.64 arc(189.26,20.76) 189.48,20.8 194.63,20.8 arc(195.21,20.92) 195.71,21.24 215.58,41.12 arc(216,41.4) 216.5,41.5 224.9,41.5 arc(225.31,41.58) 225.65,41.81 225.66,41.82 arc(225.89,42.16) 225.97,42.56 225.97,43.24 arc(226.03,43.54) 226.2,43.79 226.21,43.8 arc(226.46,43.97) 226.76,44.03 227.85,44.03 arc(228.03,43.96) 228.1,43.78 v1(228.1,43.51)
RX_05_N: length 43.9
  TOP w0.114: CAB64.1 186.58,31.18 arc(186.73,31.09) 186.9,31.05 186.93,31.05 arc(187.1,31.09) 187.25,31.18 LAB52.2 187.69,31.23 arc(187.88,31.1) 188.12,31.05 188.37,31.05 arc(188.57,31.09) 188.74,31.21 v1(188.91,31.38) ; J1.G38 v1(223.02,44.78)
  ART10 w0.102: v1(188.91,31.38) 189.08,31.2 arc(189.26,31.08) 189.48,31.04 198.31,31.04 arc(199.09,31.19) 199.75,31.64 211.36,43.24 arc(212.49,44) 213.83,44.27 222.77,44.27 arc(222.95,44.34) 223.02,44.51 v1(223.02,44.78)
RX_05_P: length 43.9
  TOP w0.114: v1(188.91,30.46) 188.74,30.63 arc(188.57,30.74) 188.37,30.78 188.12,30.78 arc(187.88,30.74) 187.69,30.61 LAB52.1 187.25,30.65 arc(187.1,30.75) 186.93,30.78 186.9,30.78 arc(186.73,30.75) 186.58,30.65 CAB66.1 ; J1.F38 v1(223.02,43.51)
  ART10 w0.102: v1(223.02,43.51) 223.02,43.78 arc(222.95,43.96) 222.77,44.03 213.83,44.03 arc(212.58,43.78) 211.53,43.07 199.92,31.47 arc(199.18,30.97) 198.31,30.8 189.48,30.8 arc(189.26,30.76) 189.08,30.64 v1(188.91,30.46)
RX_06_N: length 47.7
  TOP w0.114: CAB67.1 186.58,41.18 arc(186.73,41.09) 186.9,41.05 186.93,41.05 arc(187.1,41.09) 187.25,41.18 LAB54.2 187.69,41.23 arc(187.88,41.1) 188.12,41.05 188.37,41.05 arc(188.57,41.09) 188.74,41.21 v1(188.91,41.38) ; J1.C34 v1(228.1,49.86)
  ART10 w0.102: v1(188.91,41.38) 189.1,41.19 arc(189.26,41.08) 189.44,41.04 arc(189.45,41.04) 189.46,41.04 203.68,41.04 arc(204.07,41.11) 204.41,41.34 209.24,46.18 arc(209.95,46.65) 210.79,46.81 224.9,46.81 arc(225.21,46.88) 225.48,47.05 225.5,47.07 arc(225.67,47.33) 225.73,47.64 225.73,48.32 arc(225.81,48.71) 226.03,49.03 226.05,49.05 arc(226.37,49.27) 226.76,49.35 227.85,49.35 arc(228.03,49.42) 228.1,49.59 v1(228.1,49.86)
RX_06_P: length 47.7
  TOP w0.114: v1(188.91,40.46) 188.74,40.63 arc(188.57,40.74) 188.37,40.78 188.12,40.78 arc(187.88,40.74) 187.69,40.61 LAB54.1 187.25,40.65 arc(187.1,40.75) 186.93,40.78 186.9,40.78 arc(186.73,40.75) 186.58,40.65 CAB69.1 ; J1.B34 v1(228.1,48.59)
  ART10 w0.102: v1(228.1,48.59) 228.1,48.86 arc(228.03,49.04) 227.85,49.11 226.76,49.11 arc(226.46,49.05) 226.21,48.88 226.2,48.87 arc(226.03,48.62) 225.97,48.32 225.97,47.64 arc(225.89,47.24) 225.66,46.9 225.65,46.89 arc(225.31,46.66) 224.9,46.58 210.79,46.58 arc(210.04,46.43) 209.41,46.01 204.57,41.17 arc(204.16,40.9) 203.68,40.8 189.48,40.8 arc(189.26,40.76) 189.08,40.64 v1(188.91,40.46)
RX_07_N: length 39.2
  TOP w0.114: J1.G34 v1(223.02,49.86) ; v1(188.91,51.38) 188.74,51.21 arc(188.57,51.09) 188.37,51.05 188.1,51.05 arc(187.88,51.1) 187.7,51.22 LAB56.2 187.25,51.18 arc(187.1,51.09) 186.93,51.05 186.9,51.05 arc(186.73,51.09) 186.58,51.18 CAB70.1
  ART10 w0.102: v1(188.91,51.38) 189.1,51.19 arc(189.26,51.07) 189.46,51.04 193.04,51.04 arc(193.75,50.9) 194.35,50.5 195.07,49.78 arc(195.54,49.46) 196.11,49.35 222.77,49.35 arc(222.95,49.42) 223.02,49.59 v1(223.02,49.86)
RX_07_P: length 39.2
  TOP w0.114: v1(188.91,50.46) 188.74,50.63 arc(188.57,50.74) 188.37,50.78 188.1,50.78 arc(187.88,50.74) 187.7,50.62 LAB56.1 187.25,50.65 arc(187.1,50.75) 186.93,50.78 186.9,50.78 arc(186.73,50.75) 186.58,50.65 CAB72.1 ; J1.F34 v1(223.02,48.59)
  ART10 w0.102: v1(188.91,50.46) 189.1,50.65 arc(189.26,50.76) 189.46,50.8 193.04,50.8 arc(193.66,50.68) 194.18,50.33 194.9,49.61 arc(195.45,49.24) 196.11,49.11 222.77,49.11 arc(222.95,49.04) 223.02,48.86 v1(223.02,48.59)
RXD_GPS: length 216.9
  TOP w0.173: v1(234.11,-23.89) 233.95,-23.73 RG3.1 ; J2.C7 v1(327.06,84.15)
  ART10 w0.135: v1(234.11,-23.89) 235.06,-22.94 240.32,-22.94 243.58,-26.2 267.31,-26.2 270.97,-22.54 277.58,-22.54 281.07,-26.03 314.83,-26.03 318.64,-22.22 318.64,62.84 319.05,63.25 330.62,63.25 332.19,64.82 332.19,83.44 330.92,84.71 327.62,84.71 v1(327.06,84.15)
SDIO_CLK: length 171.7
  TOP w0.173: J3.5 394.74,23.13 394.74,23.14 v1(395.6,23.14) ; J2.G13 v1(320.71,76.53)
  ART05 w0.14: v1(320.71,76.53) 320.09,76.53 317.6,79.02 317.6,96.44 323.7,102.54 331.32,102.54 333.98,99.87 376.4,99.87 388.52,87.76 388.52,55.43 391.59,52.36 391.59,40.08 392.07,39.6 393.42,39.6 394.09,38.92 394.09,24.64 v1(395.6,23.14)
SDIO_CMD: length 141
  TOP w0.173: v1(392.01,24.23) 393.12,25.34 394.08,25.34 J3.3 ; J2.C13 v1(325.79,76.53)
  ART05 w0.14: v1(325.79,76.53) 325.36,76.96 325.36,78.15 325.51,78.3 329.67,78.3 332.08,80.71 332.08,88.7 336.14,92.76 361.16,92.76 369.8,84.12 369.8,68.38 368.18,66.76 368.18,59.24 370.04,57.38 370.04,54.24 371.3,52.98 375.73,52.98 376.64,52.08 379,52.08 380.12,50.96 380.12,48.11 382.12,46.12 382.12,43.33 382.32,43.13 386.43,43.13 387.5,42.06 387.5,34.14 388.42,33.22 388.42,27.83 v1(392.01,24.23)
SDIO_DAT0: length 127.8
  TOP w0.173: J3.7 393.57,20.94 393.57,20.94 392.02,20.94 v1(392.01,20.93) ; J2.D12 v1(325.79,77.8)
  ART05 w0.14: v1(392.01,20.93) 386.96,25.98 386.96,40.06 386.33,40.69 386.33,41.55 385.37,42.52 382.21,42.52 381.65,43.08 381.65,44.21 379.96,45.9 373.04,45.9 370.53,48.42 370.53,53 369.36,54.17 369.36,57.11 367.57,58.89 367.57,67.42 369.16,69.01 369.16,78.92 362.43,85.65 355.57,85.65 354.81,84.89 338.64,84.89 330.86,77.11 326.49,77.11 v1(325.79,77.8)
SDIO_DAT1: length 157
  TOP w0.173: v1(393.01,19.83) 393.8,19.83 393.8,19.83 J3.8 ; J2.E14 v1(323.25,75.26)
  ART05 w0.14: v1(393.01,19.83) 393.47,20.29 393.47,23.67 389,28.14 389,33.38 388.04,34.34 388.04,42.44 388.49,42.9 388.49,51.21 385.4,54.3 385.4,82.24 370.81,96.82 334.62,96.82 331.06,93.27 326.62,93.27 323.77,90.42 323.77,86.59 322.58,85.39 322.58,80.31 321.49,79.22 321.49,78.87 321.71,78.64 323.13,78.64 323.8,77.97 323.8,75.81 v1(323.25,75.26)
SDIO_DAT2: length 153.7
  TOP w0.173: J3.1 394.3,27.54 v1(393.01,27.54) ; J2.F13 v1(321.98,76.53)
  ART05 w0.14: v1(393.01,27.54) 392.35,28.19 392.35,31.95 389.23,35.08 389.23,39.19 390.02,39.98 390.02,51.96 387.31,54.68 387.31,62.33 386.91,62.72 386.91,83.52 372.34,98.1 333.86,98.1 332.52,96.76 323.51,96.76 320.14,93.4 320.14,79.02 321.98,77.18 v1(321.98,76.53)
SDIO_DAT3: length 167.1
  TOP w0.173: J2.D14 v1(324.52,75.26) ; v1(393.01,26.44) 394.11,26.44 394.11,26.43 J3.2
  ART05 w0.14: v1(393.01,26.44) 393.59,27.01 393.59,33.78 389.74,37.64 389.74,38.94 390.81,40.01 390.81,52.2 387.98,55.02 387.98,86.9 376.15,98.73 333.35,98.73 332.46,97.84 322.68,97.84 319,94.16 319,78.88 321.44,76.44 321.44,74.94 321.55,74.83 323.68,74.83 324.11,75.26 v1(324.52,75.26)
  BOTTOM w0.173: v1(393.01,26.44) 393.29,26.44 R2.2
SDIO_DETECT: length 164.1
  TOP w0.173: J3.9 394.3,18.73 393.05,18.73 392.64,19.14 R1.2 v1(391.66,19.76) ; J2.E12 v1(323.25,77.8)
  ART05 w0.14: v1(323.25,77.8) 322.82,78.23 321.67,78.23 321.18,78.71 321.18,86.69 321.67,87.17 322.45,87.17 322.71,87.43 322.71,94.28 323.84,95.42 332.19,95.42 334.24,97.46 371.45,97.46 386.33,82.58 386.33,62.34 386.73,61.95 386.73,54.12 389.28,51.56 389.28,42.67 388.7,42.09 388.7,34.87 390.32,33.25 390.32,27.66 394.26,23.72 394.26,20.04 393.39,19.17 392.25,19.17 v1(391.66,19.76)
SFP_VCCRX: length 3
  TOP w0.381: v1(370.06,130.05) v1(368.99,130.05) 368.62,129.67 J40.15
  vias: v1(361.54,130.61) v1(361.54,129.61)
SFP_VCCTX: length 3
  TOP w0.381: J40.16 368.58,128.87 v1(368.99,128.46) v1(370.06,128.46)
  vias: v1(361.54,128.26) v1(361.54,127.26)
SYS_CLK_OUT_N: length 174.8
  TOP w0.173: J2.C4 v1(327.06,87.96)
  ART03 w0.102: v1(327.06,87.96) 327.48,87.96 327.58,88.06 327.58,88.44 327.48,88.54 318.96,88.54 318.84,88.42 318.84,88.38 318.72,88.26 318.56,88.26 318.44,88.38 318.44,88.42 318.32,88.54 318.15,88.54 318.03,88.42 318.03,88.38 317.91,88.26 317.74,88.26 317.62,88.38 317.62,88.42 317.5,88.54 317.34,88.54 317.22,88.42 317.22,88.38 317.1,88.26 316.93,88.26 316.81,88.38 316.81,88.42 316.69,88.54 316.52,88.54 316.4,88.42 316.4,88.38 316.28,88.26 316.12,88.26 316,88.38 316,88.42 315.88,88.54 315.71,88.54 315.59,88.42 315.59,88.38 315.47,88.26 315.3,88.26 315.18,88.38 315.18,88.42 315.07,88.54 314.9,88.54 314.78,88.42 314.78,88.38 314.66,88.26 314.49,88.26 314.37,88.38 314.37,88.42 314.25,88.54 313.48,88.54 310.46,91.55 287.06,91.55 254.99,59.49 254.99,-4.34 253.17,-6.17 253.17,-21.36 arc(253.19,-21.47) 253.26,-21.57 v1(253.5,-21.82)
  BOTTOM w0.114: v1(253.5,-21.82) 253.18,-22.15 253.18,-22.66 253.54,-23.02 CAB76.2
SYS_CLK_OUT_P: length 174.9
  TOP w0.173: J2.B4 v1(328.33,87.96)
  ART03 w0.102: v1(252.59,-21.82) 252.84,-21.57 arc(252.91,-21.47) 252.93,-21.36 252.93,-6.07 254.76,-4.24 254.76,59.59 286.96,91.79 310.56,91.79 313.57,88.78 327.58,88.78 327.82,88.54 327.82,88.06 327.92,87.96 v1(328.33,87.96)
  BOTTOM w0.114: R93.2 R94.1 252.55,-23.02 252.91,-22.66 252.91,-22.15 v1(252.59,-21.82)
SYS_RESET#: length 133.6
  TOP w0.173: J2.B27 v1(328.33,57.48)
  ART05 w0.14: v1(328.33,57.48) 329.03,56.78 329.03,53.01 339.16,42.88 339.16,17 348.11,8.05 375.01,8.05 376.4,6.65 376.4,-8.2 382.26,-14.06 SWC4.1
SYSREF_IN_N: length 155.6
  TOP w0.173: J2.E5 v1(324.52,86.69)
  ART03 w0.102: v1(265.39,-20.27) 265.64,-20.02 arc(265.71,-19.92) 265.73,-19.8 265.73,-7.73 262.89,-4.89 262.89,56.93 292.13,86.18 324.42,86.18 arc(324.49,86.21) 324.52,86.28 v1(324.52,86.69)
  BOTTOM w0.114: v1(265.39,-20.27) 265.72,-20.59 265.72,-21.11 265.35,-21.47 CAB73.2
SYSREF_IN_P: length 155.5
  TOP w0.173: J2.D5 v1(324.52,85.42)
  ART03 w0.102: v1(324.52,85.42) 324.52,85.84 arc(324.49,85.91) 324.42,85.94 318.95,85.94 318.76,85.75 318.54,85.75 318.35,85.94 318.13,85.94 317.95,85.75 317.73,85.75 317.54,85.94 292.23,85.94 263.13,56.83 263.13,-4.79 265.97,-7.63 265.97,-19.8 arc(265.99,-19.92) 266.06,-20.02 v1(266.31,-20.27)
  BOTTOM w0.114: R89.2 266.34,-21.47 265.98,-21.11 265.98,-20.59 v1(266.31,-20.27)
TRIG_IN: length 125
  TOP w0.173: J1.C7 v1(228.1,84.15)
  ART10 w0.135: v1(228.1,84.15) 228.75,83.5 231.46,83.5 238.71,76.25 238.71,25.13 220.77,7.19 220.77,-11.35 214.51,-17.61 v1(214.51,-22.26)
  BOTTOM w0.173: v1(214.51,-22.26) 214.47,-22.3 R76.1
TRIG_OUT: length 125.8
  TOP w0.173: J1.B7 v1(229.37,84.15)
  ART10 w0.135: v1(215.43,-22.26) 215.43,-18.66 221.68,-12.41 221.68,6.35 239.89,24.55 239.89,76.8 231.98,84.71 229.92,84.71 v1(229.37,84.15)
  BOTTOM w0.173: v1(215.43,-22.26) 215.47,-22.3 R82.1
TX_00_N: length 50.2
  TOP w0.114: J1.C30 228.1,54.94 ; 187.76,61.38 187.59,61.21 arc(187.42,61.09) 187.22,61.05 186.95,61.05 arc(186.73,61.1) 186.55,61.22 LAB3.2 186.11,61.19 arc(185.95,61.09) 185.77,61.05 185.75,61.05 arc(185.57,61.09) 185.41,61.19 LAB2.2
  ART03 w0.102: 187.76,61.38 187.94,61.2 arc(188.12,61.08) 188.33,61.04 195.77,61.04 arc(196.16,60.96) 196.49,60.74 205.11,52.12 arc(205.36,51.95) 205.66,51.89 224.75,51.89 arc(225.05,51.95) 225.3,52.12 225.47,52.29 arc(225.63,52.54) 225.69,52.84 225.69,53.24 arc(225.78,53.69) 226.04,54.08 arc(226.43,54.34) 226.88,54.43 227.85,54.43 arc(228.03,54.5) 228.1,54.67 228.1,54.94
TX_00_P: length 50.2
  TOP w0.114: LAB4.2 185.41,60.65 arc(185.57,60.75) 185.75,60.78 185.77,60.78 arc(185.95,60.75) 186.11,60.65 LAB3.1 186.55,60.62 arc(186.73,60.74) 186.95,60.78 187.22,60.78 arc(187.42,60.74) 187.59,60.63 187.76,60.46 ; J1.B30 228.1,53.67
  ART03 w0.102: 187.76,60.46 187.94,60.64 arc(188.12,60.76) 188.33,60.8 195.77,60.8 arc(196.07,60.74) 196.32,60.57 204.94,51.95 arc(205.27,51.73) 205.66,51.65 224.75,51.65 arc(225.14,51.73) 225.47,51.95 225.63,52.12 arc(225.85,52.45) 225.93,52.84 225.93,53.24 arc(226,53.6) 226.21,53.91 226.21,53.91 arc(226.52,54.12) 226.88,54.19 227.85,54.19 arc(228.03,54.12) 228.1,53.94 228.1,53.67
TX_01_N: length 47.8
  TOP w0.114: J1.G30 223.02,54.94 ; 187.76,71.38 187.59,71.21 arc(187.42,71.09) 187.22,71.05 186.95,71.05 arc(186.73,71.1) 186.55,71.22 LAB8.2 186.11,71.19 arc(185.95,71.09) 185.77,71.05 185.75,71.05 arc(185.57,71.09) 185.41,71.19 LAB7.2
  ART03 w0.102: 187.76,71.38 187.94,71.2 arc(188.12,71.08) 188.33,71.04 192.43,71.04 arc(192.82,70.96) 193.15,70.74 196.89,66.99 arc(197.11,66.66) 197.19,66.28 197.19,64.78 arc(197.25,64.49) 197.42,64.23 207,54.65 arc(207.25,54.48) 207.55,54.43 222.77,54.43 arc(222.95,54.5) 223.02,54.67 223.02,54.94
TX_01_P: length 47.8
  TOP w0.114: J1.F30 223.02,53.67 ; 187.76,70.46 187.59,70.63 arc(187.42,70.74) 187.22,70.78 186.95,70.78 arc(186.73,70.74) 186.55,70.62 LAB8.1 186.11,70.65 arc(185.95,70.75) 185.77,70.78 185.75,70.78 arc(185.57,70.75) 185.41,70.65 LAB9.2
  ART03 w0.102: 223.02,53.67 223.02,53.94 arc(222.95,54.12) 222.77,54.19 207.55,54.19 arc(207.16,54.27) 206.83,54.49 197.25,64.07 arc(197.03,64.4) 196.95,64.78 196.95,66.28 arc(196.89,66.57) 196.72,66.83 192.98,70.57 arc(192.73,70.74) 192.43,70.8 188.33,70.8 arc(188.12,70.76) 187.94,70.64 187.76,70.46
TX_02_N: length 56.5
  TOP w0.114: LAB12.2 185.45,81.15 arc(185.56,81.08) 185.7,81.05 185.83,81.05 arc(185.96,81.08) 186.07,81.15 LAB13.2 186.62,81.15 arc(186.73,81.08) 186.86,81.05 187.29,81.05 arc(187.42,81.08) 187.54,81.15 187.76,81.38 ; J1.C26 228.1,60.02
  ART03 w0.102: 228.1,60.02 228.1,59.75 arc(228.03,59.58) 227.85,59.51 226.57,59.51 arc(226.21,59.43) 225.91,59.23 225.89,59.21 arc(225.69,58.91) 225.61,58.55 225.61,57.78 arc(225.56,57.48) 225.39,57.23 225.37,57.21 arc(225.12,57.04) 224.82,56.98 217.54,56.98 arc(217.24,57.04) 216.99,57.21 193.46,80.74 arc(193.13,80.96) 192.74,81.04 188.33,81.04 arc(188.12,81.08) 187.94,81.2 187.76,81.38
TX_02_P: length 56.5
  TOP w0.114: J1.B26 228.1,58.75 ; 187.76,80.46 187.54,80.68 arc(187.42,80.76) 187.29,80.78 186.86,80.78 arc(186.73,80.76) 186.62,80.68 LAB13.1 186.07,80.68 arc(185.96,80.76) 185.83,80.78 185.7,80.78 arc(185.56,80.76) 185.45,80.68 LAB14.2
  ART03 w0.102: 228.1,58.75 228.1,59.02 arc(228.03,59.2) 227.85,59.27 226.57,59.27 arc(226.3,59.22) 226.07,59.06 226.06,59.05 arc(225.9,58.82) 225.85,58.55 225.85,57.78 arc(225.77,57.39) 225.55,57.06 225.54,57.04 arc(225.21,56.82) 224.82,56.74 217.54,56.74 arc(217.15,56.82) 216.82,57.04 193.29,80.57 arc(193.04,80.74) 192.74,80.8 188.33,80.8 arc(188.12,80.76) 187.94,80.64 187.76,80.46
